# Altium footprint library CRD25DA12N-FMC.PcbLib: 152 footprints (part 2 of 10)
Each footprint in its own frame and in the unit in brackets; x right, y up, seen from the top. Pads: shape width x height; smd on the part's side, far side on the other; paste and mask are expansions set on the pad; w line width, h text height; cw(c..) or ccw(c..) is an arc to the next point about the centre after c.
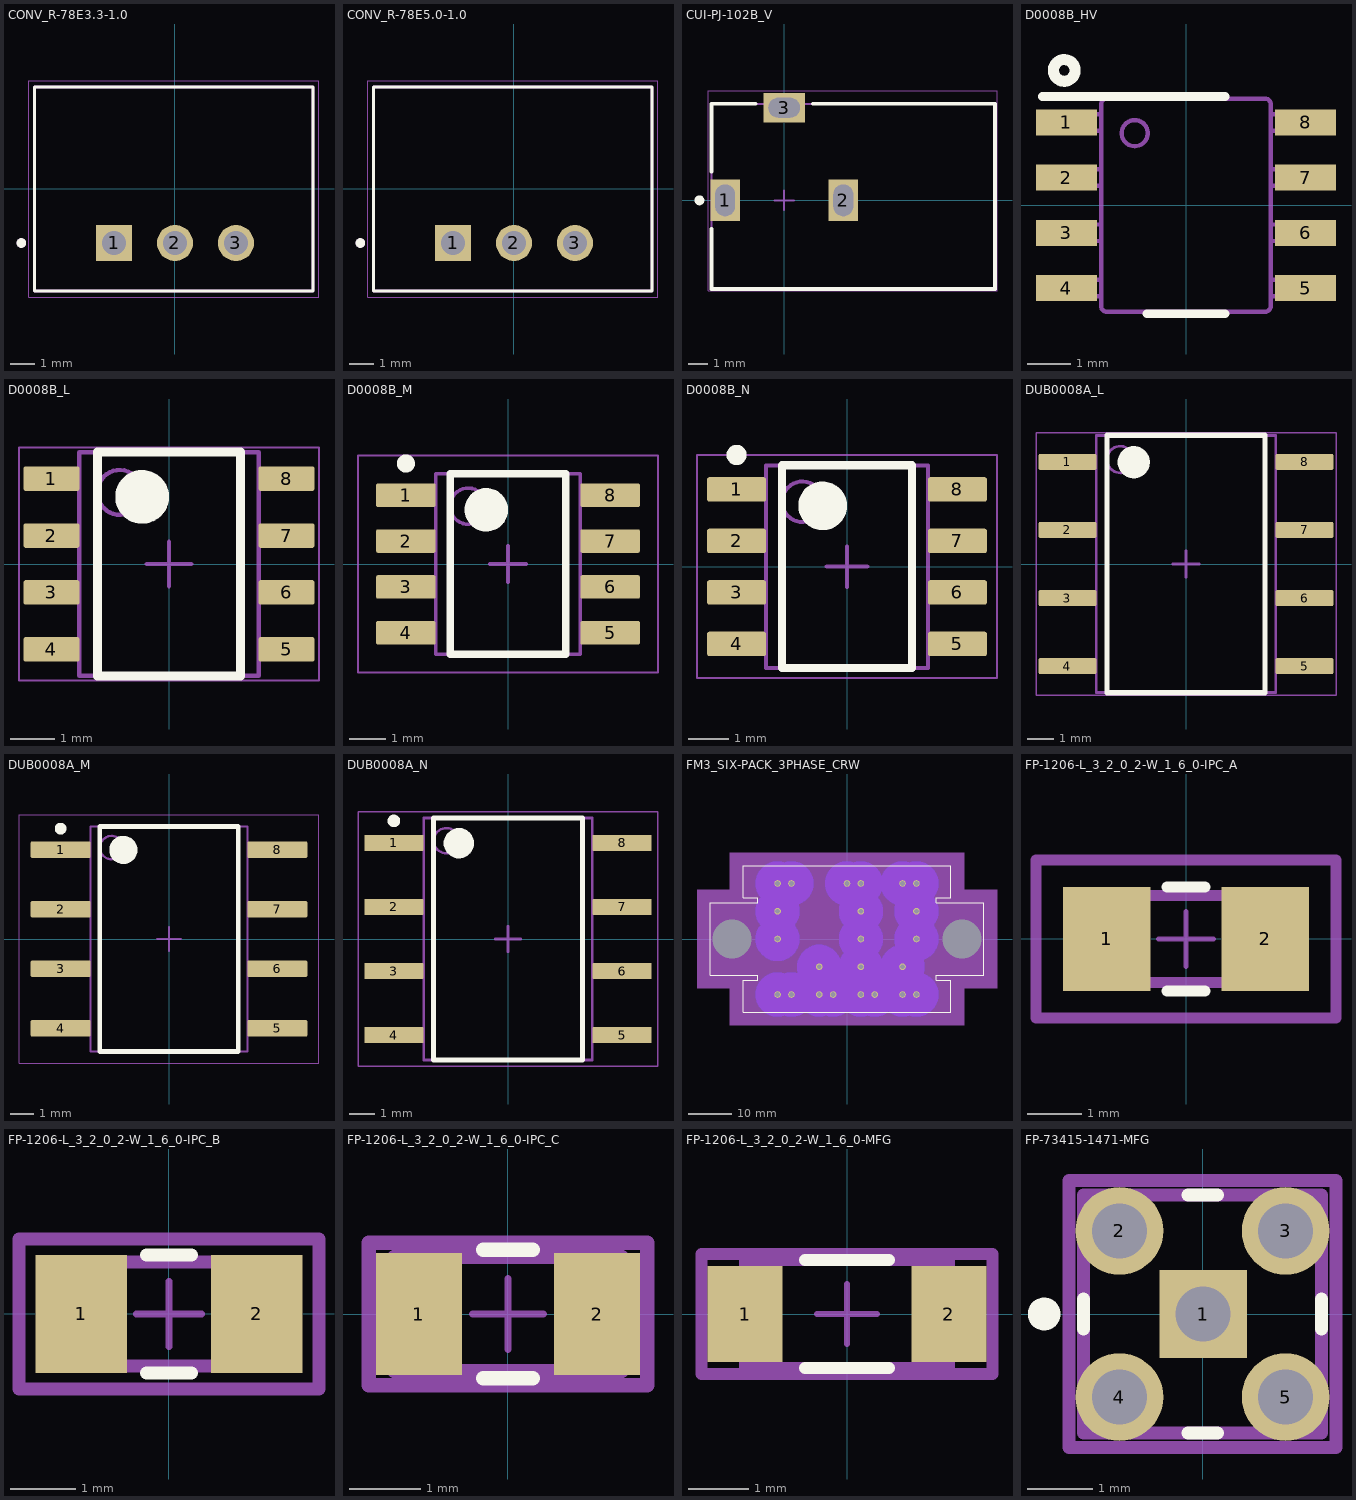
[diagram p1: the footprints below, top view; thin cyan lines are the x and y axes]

## CONV_R-78E3.3-1.0 [mm]
pads (3):
  rect 1.508x1.508 hole 1: 1(-2.54,-2.25)
  round 1.508 hole 1: 2(0,-2.25) 3(2.54,-2.25)
Top Overlay:
  circle w0.2: c-6.4,-2.25 r0.1
  lines w0.127: -5.85,-4.25 -5.85,4.25 5.75,4.25 5.75,-4.25 -5.85,-4.25
Top Designator:
  text ".Designator" at 7.33,0.508 h1.52
Mechanical 13:
  circle w0.2: c-6.4,-2.25 r0.1
  lines w0.127: -5.85,-4.25 -5.85,4.25 5.75,4.25 5.75,-4.25 -5.85,-4.25
Mechanical 15:
  lines w0.05: -6.1,-4.5 -6.1,4.5 6,4.5 6,-4.5 -6.1,-4.5
3D body "step_temp.STEP": height 9.9, standoff -4.6, extent -5.8,-4.25 5.8,4.25

## CONV_R-78E5.0-1.0 [mm]
pads (3):
  rect 1.508x1.508 hole 1: 1(-2.54,-2.25)
  round 1.508 hole 1: 2(0,-2.25) 3(2.54,-2.25)
Top Overlay:
  circle w0.2: c-6.4,-2.25 r0.1
  lines w0.127: -5.85,-4.25 -5.85,4.25 5.75,4.25 5.75,-4.25 -5.85,-4.25
Top Designator:
  text ".Designator" at 7.33,0.508 h1.52
Mechanical 13:
  circle w0.2: c-6.4,-2.25 r0.1
  lines w0.127: -5.85,-4.25 -5.85,4.25 5.75,4.25 5.75,-4.25 -5.85,-4.25
Mechanical 15:
  lines w0.05: -6.1,-4.5 -6.1,4.5 6,4.5 6,-4.5 -6.1,-4.5
3D body "step_temp.STEP": height 9.9, standoff -4.6, extent -5.8,-4.25 5.8,4.25

## CUI-PJ-102B_V [mm] "THD, 3-Leads, Body 14.4x9mm, Height 11mm"
height 11
pads (3):
  rect 1.5x2.1 hole 1 slot 1.6 at 90 deg: 1(-3,0) 2(3,0)
  rect 2.1x1.5 hole 1 slot 1.6 at 0 deg: 3(0,4.7)
Top Overlay:
  circle w0.25: c-4.3,0 r0.125
  lines w0.2: -3.7,-1.45 -3.7,-4.5 10.7,-4.5 10.7,4.9 1.45,4.9 ; -3.7,1.45 -3.7,4.9 -1.45,4.9
Mechanical 13:
  lines w0.1: -3.7,-4.5 10.7,-4.5 10.7,4.9 -3.7,4.9 -3.7,-4.5
Mechanical 15:
  lines w0.05: -3.85,-4.6 10.8,-4.6 10.8,5.55 -3.85,5.55 -3.85,-4.6
  lines w0.1: -0.5,0 0.5,0 ; 0,-0.5 0,0.5
3D body "pj-102b.stp": height 11, standoff -3.5, extent -3.7,-4.5 10.7,4.9

## D0008B_HV [mm]
pads (8):
  rect 1.4x0.6 smd paste+0 mask+0: 1(-2.75,1.905) 2(-2.75,0.635) 3(-2.75,-0.635) 4(-2.75,-1.905) 5(2.75,-1.905) 6(2.75,-0.635) 7(2.75,0.635) 8(2.75,1.905)
Top Overlay:
  circle w0.254: c-2.8,3.1 r0.25
  lines w0.2: -3.3,2.5 0.9,2.5 ; -0.9,-2.5 0.9,-2.5
Mechanical 13:
  lines w0.1: -2.375,-2.095 -1.995,-2.095 -1.952,-2.095 -1.952,-1.715 -1.995,-1.715 -2.375,-1.715 ; -2.375,-2.095 -2.589,-2.095 -3.002,-2.095 -3.002,-1.715 -2.589,-1.715 -2.375,-1.715 ; -2.375,-2.095 -2.375,-1.715 ; -2.375,-0.825 -1.995,-0.825 -1.952,-0.825 -1.952,-0.445 -1.995,-0.445 -2.375,-0.445 ; -2.375,-0.825 -2.589,-0.825 -3.002,-0.825 -3.002,-0.445 -2.589,-0.445 -2.375,-0.445 ; -2.375,-0.825 -2.375,-0.445 ; -2.375,0.445 -1.995,0.445 -1.952,0.445 -1.952,0.825 -1.995,0.825 -2.375,0.825 ; -2.375,0.445 -2.589,0.445 -3.002,0.445 -3.002,0.825 -2.589,0.825 -2.375,0.825 ; -2.375,0.445 -2.375,0.825 ; -2.375,1.715 -1.995,1.715 -1.952,1.715 -1.952,2.095 -1.995,2.095 -2.375,2.095 ; -2.375,1.715 -2.589,1.715 -3.002,1.715 -3.002,2.095 -2.589,2.095 -2.375,2.095 ; -2.375,1.715 -2.375,2.095 ; -0.332,-2.45 -1.825,-2.45 -1.826,-2.45 cw(c-1.825,-2.323) -1.952,-2.324 -1.952,-2.323 -1.952,2.323 -1.952,2.324 cw(c-1.825,2.323) -1.826,2.45 -1.825,2.45 -0.332,2.45 ; -0.332,-2.45 -0.182,-2.45 ; -0.332,-2.45 -0.182,-2.45 ; -0.332,2.45 -0.182,2.45 ; -0.332,2.45 -0.182,2.45 ; -0.182,-2.45 0.178,-2.45 ; -0.182,2.45 0.178,2.45 ; 0.178,-2.45 0.328,-2.45 ; 0.178,-2.45 0.328,-2.45 ; 0.178,2.45 0.328,2.45 ; 0.178,2.45 0.328,2.45 ; 0.328,-2.45 1.821,-2.45 1.822,-2.45 ccw(c1.821,-2.323) 1.948,-2.324 1.948,-2.323 1.948,2.323 1.948,2.324 ccw(c1.821,2.323) 1.822,2.45 1.821,2.45 0.328,2.45 ; 2.371,-2.095 2.585,-2.095 2.998,-2.095 2.998,-1.715 2.585,-1.715 2.371,-1.715 ; 2.371,-2.095 1.991,-2.095 1.948,-2.095 1.948,-1.715 1.991,-1.715 2.371,-1.715 ; 2.371,-2.095 2.371,-1.715 ; 2.371,-0.825 2.585,-0.825 2.998,-0.825 2.998,-0.445 2.585,-0.445 2.371,-0.445 ; 2.371,-0.825 1.991,-0.825 1.948,-0.825 1.948,-0.445 1.991,-0.445 2.371,-0.445 ; 2.371,-0.825 2.371,-0.445 ; 2.371,0.445 2.585,0.445 2.998,0.445 2.998,0.825 2.585,0.825 2.371,0.825 ; 2.371,0.445 1.991,0.445 1.948,0.445 1.948,0.825 1.991,0.825 2.371,0.825 ; 2.371,0.445 2.371,0.825 ; 2.371,1.715 2.585,1.715 2.998,1.715 2.998,2.095 2.585,2.095 2.371,2.095 ; 2.371,1.715 1.991,1.715 1.948,1.715 1.948,2.095 1.991,2.095 2.371,2.095 ; 2.371,1.715 2.371,2.095 ; -1.18,1.356 cw(c-1.18,1.656) -1.18,1.956 cw(c-1.18,1.656) -1.18,1.356
3D body: height 0.25, standoff 0, extent 0,0 0.254,0.254
3D body "D0008B.stp": height 1.63, standoff 0, extent -3.011,-2.451 3.011,2.451

## D0008B_L [mm] "SOIC, 8-Leads, Body 5x4mm, Pitch 1.27mm, IPC High Density"
height 1.75
pads (8):
  rrect18% 1.25x0.55 smd: 1(-2.625,1.905) 2(-2.625,0.635) 3(-2.625,-0.635) 4(-2.625,-1.905) 5(2.625,-1.905) 6(2.625,-0.635) 7(2.625,0.635) 8(2.625,1.905)
Top Overlay:
  circle w0.6: c-0.6,1.5 r0.3
  lines w0.2: -1.6,-2.5 -1.6,2.5 1.6,2.5 1.6,-2.5 -1.6,-2.5
Mechanical 1:
  text ".Designator" at -1.397,-0.254 h0.6
Mechanical 13:
  circle w0.1: c-1.1,1.6 r0.5
  lines w0.1: -2,-2.5 -2,2.5 2,2.5 2,-2.5 -2,-2.5
Mechanical 15:
  lines w0.05: -3.35,-2.6 -3.35,2.6 3.35,2.6 3.35,-2.6 -3.35,-2.6
  lines w0.1: -0.5,0 0.5,0 ; 0,-0.5 0,0.5
3D body "SOIC-8akaD0008AakaM08A.stp": height 1.63, standoff 0, extent -3,-2.45 3,2.45

## D0008B_M [mm] "SOIC, 8-Leads, Body 5x4mm, Pitch 1.27mm, IPC Low Density"
height 1.75
pads (8):
  rrect15% 1.65x0.65 smd: 1(-2.825,1.905) 2(-2.825,0.635) 3(-2.825,-0.635) 4(-2.825,-1.905) 5(2.825,-1.905) 6(2.825,-0.635) 7(2.825,0.635) 8(2.825,1.905)
Top Overlay:
  circle w0.6: c-0.6,1.5 r0.3
  circle w0.25: c-2.825,2.78 r0.125
  lines w0.2: -1.6,-2.5 1.6,-2.5 1.6,2.5 -1.6,2.5 -1.6,-2.5
Mechanical 1:
  text ".Designator" at -1.397,-0.254 h0.6
Mechanical 13:
  circle w0.1: c-1.1,1.6 r0.5
  lines w0.1: -2,-2.5 2,-2.5 2,2.5 -2,2.5 -2,-2.5
Mechanical 15:
  lines w0.05: -4.15,-3 4.15,-3 4.15,3 -4.15,3 -4.15,-3
  lines w0.1: -0.5,0 0.5,0 ; 0,-0.5 0,0.5
3D body "SOIC-8akaD0008AakaM08A.stp": height 1.63, standoff 0, extent -3,-2.45 3,2.45

## D0008B_N [mm] "SOIC, 8-Leads, Body 5x4mm, Pitch 1.27mm, IPC Medium Density"
height 1.75
pads (8):
  rrect17% 1.45x0.6 smd: 1(-2.725,1.905) 2(-2.725,0.635) 3(-2.725,-0.635) 4(-2.725,-1.905) 5(2.725,-1.905) 6(2.725,-0.635) 7(2.725,0.635) 8(2.725,1.905)
Top Overlay:
  circle w0.25: c-2.725,2.755 r0.125
  circle w0.6: c-0.6,1.5 r0.3
  lines w0.2: -1.6,-2.5 -1.6,2.5 1.6,2.5 1.6,-2.5 -1.6,-2.5
Mechanical 1:
  text ".Designator" at -1.397,-0.254 h0.6
Mechanical 13:
  circle w0.1: c-1.1,1.6 r0.5
  lines w0.1: -2,-2.5 -2,2.5 2,2.5 2,-2.5 -2,-2.5
Mechanical 15:
  lines w0.05: -3.7,-2.75 -3.7,2.75 3.7,2.75 3.7,-2.75 -3.7,-2.75
  lines w0.1: -0.5,0 0.5,0 ; 0,-0.5 0,0.5
3D body "SOIC-8akaD0008AakaM08A.stp": height 1.63, standoff 0, extent -3,-2.45 3,2.45

## DUB0008A_L [mm] "SOP, 8-Leads, Body 6.7x9.6mm, Pitch 2.54mm, IPC High Density"
height 4.85
pads (8):
  rrect17% 2.15x0.6 smd: 1(-4.425,3.81) 2(-4.425,1.27) 3(-4.425,-1.27) 4(-4.425,-3.81) 5(4.425,-3.81) 6(4.425,-1.27) 7(4.425,1.27) 8(4.425,3.81)
Top Overlay:
  circle w0.6: c-1.95,3.8 r0.3
  lines w0.2: -2.95,-4.8 -2.95,4.8 2.95,4.8 2.95,-4.8 -2.95,-4.8
Mechanical 1:
  text ".Designator" at -2.286,-0.381 h1
Mechanical 13:
  circle w0.1: c-2.45,3.9 r0.5
  lines w0.1: -3.35,-4.8 -3.35,4.8 3.35,4.8 3.35,-4.8 -3.35,-4.8
Mechanical 15:
  lines w0.05: -5.6,-4.9 -5.6,4.9 5.6,4.9 5.6,-4.9 -5.6,-4.9
  lines w0.1: -0.5,0 0.5,0 ; 0,-0.5 0,0.5
3D body "DUB0008A.stp": height 4.85, standoff 0, extent -5.242,-4.75 5.242,4.75

## DUB0008A_M [mm] "SOP, 8-Leads, Body 6.7x9.6mm, Pitch 2.54mm, IPC Low Density"
height 4.85
pads (8):
  rrect14% 2.55x0.7 smd: 1(-4.625,3.81) 2(-4.625,1.27) 3(-4.625,-1.27) 4(-4.625,-3.81) 5(4.625,-3.81) 6(4.625,-1.27) 7(4.625,1.27) 8(4.625,3.81)
Top Overlay:
  circle w0.6: c-1.95,3.8 r0.3
  circle w0.25: c-4.625,4.71 r0.125
  lines w0.2: -2.95,-4.8 2.95,-4.8 2.95,4.8 -2.95,4.8 -2.95,-4.8
Mechanical 1:
  text ".Designator" at -2.286,-0.254 h1
Mechanical 13:
  circle w0.1: c-2.45,3.9 r0.5
  lines w0.1: -3.35,-4.8 3.35,-4.8 3.35,4.8 -3.35,4.8 -3.35,-4.8
Mechanical 15:
  lines w0.05: -6.4,-5.3 6.4,-5.3 6.4,5.3 -6.4,5.3 -6.4,-5.3
  lines w0.1: -0.5,0 0.5,0 ; 0,-0.5 0,0.5
3D body "DUB0008A.stp": height 4.85, standoff 0, extent -5.242,-4.75 5.242,4.75

## DUB0008A_N [mm] "SOP, 8-Leads, Body 6.7x9.6mm, Pitch 2.54mm, IPC Medium Density"
height 4.85
pads (8):
  rrect15% 2.35x0.65 smd: 1(-4.525,3.81) 2(-4.525,1.27) 3(-4.525,-1.27) 4(-4.525,-3.81) 5(4.525,-3.81) 6(4.525,-1.27) 7(4.525,1.27) 8(4.525,3.81)
Top Overlay:
  circle w0.25: c-4.525,4.685 r0.125
  circle w0.6: c-1.95,3.8 r0.3
  lines w0.2: -2.95,-4.8 -2.95,4.8 2.95,4.8 2.95,-4.8 -2.95,-4.8
Mechanical 1:
  text ".Designator" at -2.54,-0.254 h1
Mechanical 13:
  circle w0.1: c-2.45,3.9 r0.5
  lines w0.1: -3.35,-4.8 -3.35,4.8 3.35,4.8 3.35,-4.8 -3.35,-4.8
Mechanical 15:
  lines w0.05: -5.95,-5.05 -5.95,5.05 5.95,5.05 5.95,-5.05 -5.95,-5.05
  lines w0.1: -0.5,0 0.5,0 ; 0,-0.5 0,0.5
3D body "DUB0008A.stp": height 4.85, standoff 0, extent -5.242,-4.75 5.242,4.75

## FM3_SIX-PACK_3PHASE_CRW [mm]
pads (25):
  round 1.524 hole 1.1: DC+_1(-6.4,-6.4) DC+_2(3.2,-6.4) DC+_3(12.8,-6.4) DC-1(-16,0) DC-2(3.2,0) DC-3(16,0) G1(-12.8,-12.8) G2(-16,12.8) G3(-3.2,-12.8) G4(3.2,12.8) G5(6.4,-12.8) G6(16,12.8) NTC1(12.8,-12.8) NTC2(16,-12.8) S1(-16,-12.8) S2(-12.8,12.8) S3(-6.4,-12.8) S4(0,12.8) S5(3.2,-12.8) S6(12.8,12.8) U(-16,6.4) V(3.2,6.4) W(16,6.4)
  round 0 hole 9 unplated: MH1(-26.5,0) MH2(26.5,0)
Bottom Layer keep-out:
  circle w6.2: c3.2,0 r2
  circle w6.2: c3.2,6.4 r2
  circle w6.2: c16,6.4 r2
  circle w6.2: c16,0 r2
  circle w6.2: c12.8,-6.4 r2
  circle w6.2: c3.2,-6.4 r2
  circle w6.2: c-6.4,-6.4 r2
  circle w6.2: c-16,0 r2
  circle w6.2: c-16,6.4 r2
  circle w6.2: c-16,-12.8 r2
  circle w6.2: c-12.8,-12.8 r2
  circle w6.2: c-6.4,-12.8 r2
  circle w6.2: c-3.2,-12.8 r2
  circle w6.2: c3.2,-12.8 r2
  circle w6.2: c6.4,-12.8 r2
  circle w6.2: c12.8,-12.8 r2
  circle w6.2: c16,-12.8 r2
  circle w6.2: c3.2,12.8 r2
  circle w6.2: c12.8,12.8 r2
  circle w6.2: c0,12.8 r2
  circle w6.2: c-12.8,12.8 r2
  circle w6.2: c-16,12.8 r2
  circle w6.2: c16,12.8 r2
Top Overlay:
  lines w0.152: -31.521,-8.331 -31.521,8.331 -20.625,8.331 -20.625,9.563 -23.927,9.563 -23.927,16.878 23.927,16.878 23.927,9.563 20.625,9.563 20.625,8.331 31.521,8.331 31.521,-8.331 20.625,-8.331 20.625,-9.563 23.927,-9.563 23.927,-16.878 -23.927,-16.878 -23.927,-9.563 -20.625,-9.563 -20.625,-8.331 -31.521,-8.331
Bottom Courtyard:
  text "Default Padstyle: EX60Y60D43P0" at -9.525,-21.831 h1.27
Bottom 3D Body:
  region: 26.975,19.926 -26.975,19.926 -26.975,11.379 -34.569,11.379 -34.569,-11.379 -26.975,-11.379 -26.975,-19.926 26.975,-19.926 26.975,-11.379 34.569,-11.379 34.569,11.379 26.975,11.379
Top Designator:
  text ".Designator" at 7.618,-0.694 h1.52
Mechanical 13:
  drawing of 27 lines, arcs and shapes, not listed
Mechanical 15:
  region: 20.752,-9.436 20.752,-8.458 31.648,-8.458 31.648,8.458 20.752,8.458 20.752,9.436 24.054,9.436 24.054,17.005 -24.054,17.005 -24.054,9.436 -20.752,9.436 -20.752,8.458 -31.648,8.458 -31.648,-8.458 -20.752,-8.458 -20.752,-9.436 -24.054,-9.436 -24.054,-17.005 24.054,-17.005 24.054,-9.436
  lines w0.152: -31.648,-8.458 -31.648,8.458 -20.752,8.458 -20.752,9.436 -24.054,9.436 -24.054,17.005 24.054,17.005 24.054,9.436 20.752,9.436 20.752,8.458 31.648,8.458 31.648,-8.458 20.752,-8.458 20.752,-9.436 24.054,-9.436 24.054,-17.005 -24.054,-17.005 -24.054,-9.436 -20.752,-9.436 -20.752,-8.458 -31.648,-8.458
3D body "McMaster-Carr 93070A095 - Alternative.STEP": height -7.7, standoff -16.5, extent -30,-3.5 -23,3.5
3D body "McMaster-Carr 93070A095 - Alternative.STEP": height -7.7, standoff -16.5, extent 23,-3.5 30,3.5
3D body: height 0.25, standoff 0, extent 0,0 0.254,0.254
3D body "CCB0xxM12FM3(Six_Pack)_External_POD_20200723_Branded_Origin.STEP": height 11.98, standoff -4.42, extent -31.4,-16.9 31.4,16.9

## FP-1206-L_3_2_0_2-W_1_6_0-IPC_A [mm]
pads (2):
  rect 1.604x1.906 smd paste+0 mask+0: 1(-1.451,0) 2(1.451,0)
Top Overlay:
  lines w0.2: -0.349,-0.953 0.349,-0.953 ; -0.349,0.953 0.349,0.953
Mechanical 5:
  lines w0.2: -2.753,-1.453 2.753,-1.453 2.753,1.453 -2.753,1.453 -2.753,-1.453
  text ".Designator" at 0,0.188 h1
Mechanical 13:
  lines w0.2: -1.6,-0.8 1.6,-0.8 1.6,0.8 -1.6,0.8 -1.6,-0.8
Mechanical 15:
  lines w0.2: -2.753,-1.453 2.753,-1.453 2.753,1.453 -2.753,1.453 -2.753,-1.453
Mechanical 16:
  lines w0.1: -0.5,0 0.5,0 ; 0,-0.5 0,0.5
3D body "Cap_Taiyo_Yuden_JMK316ABJ226KLHT_eec.STEP": height 0.25, standoff 0, extent -2.753,-1.453 2.753,1.453

## FP-1206-L_3_2_0_2-W_1_6_0-IPC_B [mm]
pads (2):
  rect 1.404x1.806 smd paste+0 mask+0: 1(-1.351,0) 2(1.351,0)
Top Overlay:
  lines w0.2: -0.349,-0.903 0.349,-0.903 ; -0.349,0.903 0.349,0.903
Mechanical 5:
  lines w0.2: -2.303,-1.153 2.303,-1.153 2.303,1.153 -2.303,1.153 -2.303,-1.153
  text ".Designator" at 0,0.188 h1
Mechanical 13:
  lines w0.2: -1.6,-0.8 1.6,-0.8 1.6,0.8 -1.6,0.8 -1.6,-0.8
Mechanical 15:
  lines w0.2: -2.303,-1.153 2.303,-1.153 2.303,1.153 -2.303,1.153 -2.303,-1.153
Mechanical 16:
  lines w0.1: -0.5,0 0.5,0 ; 0,-0.5 0,0.5
3D body "Cap_Taiyo_Yuden_JMK316ABJ226KLHT_eec.STEP": height 0.25, standoff 0, extent -2.303,-1.153 2.303,1.153

## FP-1206-L_3_2_0_2-W_1_6_0-IPC_C [mm]
pads (2):
  rect 1.204x1.706 smd paste+0 mask+0: 1(-1.251,0) 2(1.251,0)
Top Overlay:
  lines w0.2: -0.349,-0.9 0.349,-0.9 ; -0.349,0.9 0.349,0.9
Mechanical 5:
  lines w0.2: -1.953,-1 1.953,-1 1.953,1 -1.953,1 -1.953,-1
  text ".Designator" at 0,0.188 h1
Mechanical 13:
  lines w0.2: -1.6,-0.8 1.6,-0.8 1.6,0.8 -1.6,0.8 -1.6,-0.8
Mechanical 15:
  lines w0.2: -1.953,-1 1.953,-1 1.953,1 -1.953,1 -1.953,-1
Mechanical 16:
  lines w0.1: -0.5,0 0.5,0 ; 0,-0.5 0,0.5
3D body "Cap_Taiyo_Yuden_JMK316ABJ226KLHT_eec.STEP": height 0.25, standoff 0, extent -1.953,-1 1.953,1

## FP-1206-L_3_2_0_2-W_1_6_0-MFG [mm]
pads (2):
  rect 1.25x1.6 smd paste+0 mask+0: 1(-1.7,0) 2(1.7,0)
Top Overlay:
  lines w0.2: -0.7,-0.9 0.7,-0.9 ; -0.7,0.9 0.7,0.9
Mechanical 5:
  lines w0.2: -2.425,-1 -2.425,1 2.425,1 2.425,-1 -2.425,-1
  text ".Designator" at 0,0.188 h1
Mechanical 13:
  lines w0.2: -1.7,-0.9 -1.7,0.9 1.7,0.9 1.7,-0.9 -1.7,-0.9
Mechanical 15:
  lines w0.2: -2.425,-1 -2.425,1 2.425,1 2.425,-1 -2.425,-1
Mechanical 16:
  lines w0.1: -0.5,0 0.5,0 ; 0,-0.5 0,0.5
3D body "Cap_Taiyo_Yuden_JMK316ABJ226KLHT_eec.STEP": height 0.25, standoff 0, extent -2.425,-1 2.425,1

## FP-73415-1471-MFG [mm]
pads (5):
  rect 1.34x1.34 hole 0.84 paste-2539.97 mask+0: 1(0.01,0)
  round 1.34 hole 0.84 paste-2539.97 mask+0: 2(-1.27,1.27) 3(1.27,1.27) 4(-1.27,-1.27) 5(1.27,-1.27)
Top Overlay:
  circle w0.25: c-2.42,0 r0.125
  lines w0.2: -1.82,-0.225 -1.82,0.225 ; -0.225,-1.82 0.225,-1.82 ; -0.225,1.82 0.225,1.82 ; 1.82,-0.225 1.82,0.225
Mechanical 5:
  lines w0.2: -2.04,-2.04 -2.04,2.04 2.04,2.04 2.04,-2.04 -2.04,-2.04
  text ".Designator" at 0,0.188 h1
Mechanical 13:
  lines w0.2: -1.82,-1.82 -1.82,1.82 1.82,1.82 1.82,-1.82 -1.82,-1.82
Mechanical 15:
  lines w0.2: -2.04,-2.04 -2.04,2.04 2.04,2.04 2.04,-2.04 -2.04,-2.04
Mechanical 16:
  lines w0.1: -0.5,0 0.5,0 ; 0,-0.5 0,0.5
3D body "Conn_Molex_73415-1471_eec.STEP": height 0.25, standoff 0, extent -2.04,-2.04 2.04,2.04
